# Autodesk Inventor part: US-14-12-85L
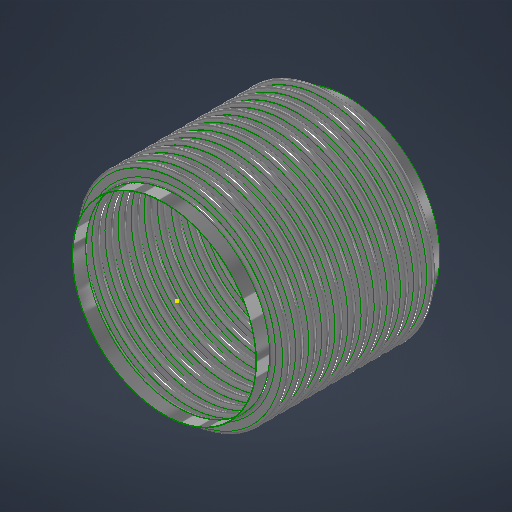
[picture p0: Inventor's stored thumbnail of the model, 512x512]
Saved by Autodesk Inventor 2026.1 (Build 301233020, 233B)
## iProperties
Category: 20 GA (0.036 THICK)
RuleStatus: InUse
Created: 2026-07
Part Number: US-14-12-85L
Project: =STOCK BELLOWS: <Stock Number><SFILL>
Material: ASTM A240-304
Description: =STOCK BELLOWS: <Stock Number>, <SID_> I.D., <SOD_> O.D., <SPLY_> PLY, <Category>, <SNET_CONS> CONS.<PITCH_><STANGENT_> TANGENT<SFILL>
Document SubType Name: Sheet Metal
Designer: LC
Stock Number: U.S-14-12-85L
Surface Area: 659.127 cm^2
Volume: 56.61 cm^3
Sheet Metal Rule: Default
Appearance: STAINLESS STEEL
NET_TUBE: 3.428
COUNTER: 1.500
PBAR: 1.214
PSET: 5.356
PLY: 2
CONS: 2
THK: 0.036
ID: 4.500
OD: 5.500
CONS_: 2
TANGENT: 0.500
PITCH: 0.375
BELLOWS_UPSET: 0.000
NET_CONS: 2
S_CONS: 0
Description_Units: 0
ID_M: 114.30 mm
OD_M: 139.70 mm
THK_M: 0.91 mm
ID_U: 4.500 in
OD_U: 5.500 in
THK_U: 0.036 in
TANGENT2: 0.500
d79: 1.000
d82: 1.000
d83: 26.000
d84: 24.000
d80: 2.571
d81: 10
SID: 2.375
SCONS_: 12
SPITCH: 0.250
SBELLOWS_UPSET: 0.000
SNET_CONS: 12
SS_CONS: 0
SCONS: 8
d174: 8
d177: 0.018
d178: 2.375
d179: 3.000
d180: 0.375
d181: 1.000
d182: 0.000
d190: 8
d191: 1
d192: 1
d193: 8
d194: 0
PART_NUMBER: U.S-14-12-85L
PRESSURE: 85
SIZE: 14.00
STANGENT_: 1.000
d214: 8
d217: 0.030
d218: 6.625
d219: 8.125
d220: 0.500
d221: 1.000
d222: 0.000
d230: 8
d231: 1
d232: 1
d233: 8
d234: 0
STANGENT: 4.000
SPLY_: 1
STHK_: 0.036
SID_: 14.000
SOD_: 16.125
SPITCH_: 1.000
STANGENT__: 1.000
SBELLOWS_UPSET_: 0.000
SDIFF_TAN: 1.000
TAN_TO_TAN: 0.750 in
d252: 2
d275: 2
d287: 0.050
d289: 0.500
d290: 0.000
d263: 2
d265: 1
d268: 2
d269: 0
d286: 2
d288: 1
d291: 2
d292: 0
SOD_NECK: 14 1/16
CFILL: .
SFILL: .
PITCH_: =, <SPITCH_> PITCH,
SREROLL: 0.750
MATTABLE: 20 GA (0.036 THICK)
MESH: ,
CSECT: 2
Author: LC
Keywords: 20 GA (0.036 THICK)
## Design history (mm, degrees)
sketch "Sketch2"
  geometry: L1 (0, -183.595)-(0, 600.956) reference; L2 (58.979, 0)-(57.15, 0); L3 (60.446, -1.467)-(66.554, -1.467); L4 (60.446, -3.296)-(66.554, -3.296); L5 (66.554, -8.058)-(60.446, -8.058); L6 (66.554, -6.229)-(60.446, -6.229); L7 (58.979, -9.525)-(57.15, -9.525); L8 (60.446, 0)-(60.446, -9.525); L9 (66.554, -4.762)-(69.85, -4.763); L10 (57.15, 0)-(57.15, -9.525); L11 (20.376, 102.841)-(20.376, 101.926); L12 (58.262, 488.877)-(58.262, 349.177); L13 (58.262, 479.352)-(58.262, 339.652); L14 (93.133, -58.817)-(93.133, -71.517); L15 (118.746, -66.401)-(118.746, -66.401); L16 (66.554, -6.229)-(66.554, -8.058); L17 (60.446, -6.229)-(60.446, -8.058); L18 (60.446, -7.144)-(66.554, -7.144); L19 (69.85, 0)-(69.85, -9.525); L20 (-66.554, -6.229)-(-66.554, -8.058); L21 (-66.554, -1.467)-(-60.446, -1.467); L22 (-66.554, -3.296)-(-60.446, -3.296); L23 (-60.446, -6.229)-(-66.554, -6.229); L24 (-66.554, -7.144)-(-60.446, -7.144); L25 (-60.446, -8.058)-(-66.554, -8.058); L26 (-60.446, -6.229)-(-60.446, -8.058); L27 (-57.15, -2.522)-(-57.15, -12.047); L28 (-60.446, -4.763)-(-57.15, -4.763); L29 (-66.554, 3.828)-(-66.554, -9.525); L30 (-68.021, 0)-(-69.85, 0); L31 (-69.85, 0)-(-69.85, -9.525); L32 (-68.021, -9.525)-(-69.85, -9.525); A1 r 1.467 centre (60.446, 0) between (58.979, 0) and (60.446, -1.467); A2 r 3.296 centre (60.446, 0) between (57.15, 0) and (60.446, -3.296); A3 r 3.296 centre (66.554, -4.762) between (66.554, -8.058) and (66.554, -1.467); A4 r 1.467 centre (66.554, -4.762) between (66.554, -6.229) and (66.554, -3.296); A5 r 1.467 centre (60.446, -9.525) between (60.446, -8.058) and (58.979, -9.525); A6 r 3.296 centre (60.446, -9.525) between (60.446, -6.229) and (57.15, -9.525); A7 r 2.381 centre (66.554, -4.762) between (66.554, -7.144) and (68.936, -4.762); A8 r 2.381 centre (60.446, -9.525) between (60.446, -7.144) and (58.064, -9.525); A9 r 1.467 centre (-66.554, -9.525) between (-66.554, -8.058) and (-68.021, -9.525); A10 r 1.467 centre (-60.446, -4.763) between (-60.446, -6.229) and (-60.446, -3.296); A11 r 2.381 centre (-60.446, -4.763) between (-60.446, -7.144) and (-58.064, -4.763); A12 r 3.296 centre (-60.446, -4.763) between (-60.446, -8.058) and (-60.446, -1.467); A13 r 2.381 centre (-66.554, -9.525) between (-66.554, -7.144) and (-68.936, -9.525); A14 r 3.296 centre (-66.554, -9.525) between (-66.554, -6.229) and (-69.85, -9.525); A15 r 1.467 centre (-66.554, 0) between (-68.021, 0) and (-66.554, -1.467); A16 r 3.296 centre (-66.554, 0) between (-69.85, 0) and (-66.554, -3.296); 10 further points
  constraints: 62 end point, 38 point on circle, 20 tangent, 16 centre point, 12 parallel, 9 midpoint, 7 vertical, 6 coincident, 6 concentric, 6 point on line, 4 equal radius, 4 perpendicular, 3 horizontal, 1 collinear, 1 horizontal alignment, 10 other
  dimensions: "THK" = 0.9144 distance of L11.start L11.end; "ID" = 114.3 distance of L11.end point (20.376, -12.374); "OD" = 139.7 distance of L12.start L12.end; "PITCH" = 9.525 distance of L12.start L13.start; "TANGENT" = 12.7 distance of L14.start L14.end; "BELLOWS_UPSET" = 0 distance of L15.start L15.end; "d43" = 114.3 diameter of L10 L1 (= ID); "d44" = 139.7 diameter of L9.end L1 (= OD); "d45" = 1.8288 distance between parallel lines of L5 L6 (computed from THK, PLY); "d46" = 3.29565 radius of A3 (computed from PITCH, THK, PLY); "UPSET_PITCH" = 9.525 distance of L2.end L7.end (derived); "SIDEWALL_ANGLE" = 0 deg angle of L3 L9 (derived); "CON_GAP" = 2.9337 distance of point (60.446, -6.229) point (60.446, -3.296) (derived); "TAN1" = 3.74046 dimension on A8 (derived); "TAN2" = 3.74046 dimension on A7 (derived); "LEG1" = 6.1087 distance of L18.start L18.end (derived); "d278" = 1.8288 distance between parallel lines of L25 L23 (derived); "d279" = 3.29565 radius of A12 (derived); "d280" = 9.525 distance of L30.end L31.end (derived); "d281" = 360 deg dimension on L21 L28 (derived); "d282" = 2.9337 distance of point (-66.554, -6.229) point (-66.554, -3.296) (derived); "d283" = 3.74046 dimension on A13 (derived); "d284" = 3.74046 dimension on A11 (derived); "d285" = 6.1087 distance of L24.start L24.end (derived); "d293" = 114.3 diameter of L27 L1 (derived); "d294" = 139.7 diameter of L31 L1 (derived)
  node "Sketch Rectangular Pattern1" dims "d31" = 25.4, "ID" = 114.3
  node "Sketch Rectangular Pattern2" dims "d39" = 25.4, "PITCH" = 9.525
revolve "CONS" stored, may be unused: angle "d48" = 90 deg
node "BELLOW MIDPLANE"
pattern_linear "Rectangular Pattern2" dims "d52" = 9.525 (= UPSET_PITCH)
sketch "Sketch5"
  geometry: C1 r 58.979 at (0, 0) reference; C2 r 57.15 at (0, 0) reference
extrude "TANGENT" new body sketch "Sketch5" distance "d53" = 12.7 (= TANGENT); taper "d54" = 0 deg
revolve "SAMETAN" stored, may be unused: angle "d65" = 90 deg
revolve "DIFFTAN" stored, may be unused: angle "d70" = 90 deg
sketch "Sketch9"
  geometry: L1 (58.391, 0)-(-58.391, 0) reference; L2 (0, -17.78)-(0, 17.78) reference; L3 (41.708, 0)-(-41.708, 0); L4 (41.708, -11.906)-(41.708, 11.906); L5 (29.008, -11.906)-(29.008, 11.906); L6 (15.418, 11.906)-(15.418, -11.906); L7 (-29.008, -11.906)-(-29.008, 11.906); L8 (-41.708, -11.906)-(-41.708, 11.906); L9 (40.914, -11.906)-(40.914, 11.906); L10 (41.708, -11.906)-(40.914, -11.906); L11 (41.708, 11.906)-(40.914, 11.906); L12 (15.815, 11.906)-(15.022, 11.906); L13 (15.022, 11.906)-(15.022, -11.906); L14 (15.022, -11.906)-(15.815, -11.906); L15 (15.815, -11.906)-(15.815, 11.906); L16 (-15.815, 11.906)-(-15.815, -11.906); L17 (-15.418, 11.906)-(-15.418, -11.906); L18 (-15.815, -11.906)-(-15.022, -11.906); L19 (-15.022, -11.906)-(-15.022, 11.906); L20 (-15.022, 11.906)-(-15.815, 11.906); L21 (-41.708, -11.906)-(-40.914, -11.906); L22 (-40.914, -11.906)-(-40.914, 11.906); L23 (-40.914, 11.906)-(-41.708, 11.906); L24 (-41.708, 11.906)-(-41.708, -11.906); L25 (41.708, -0.397)-(-41.708, -0.397); L26 (-41.708, -0.397)-(-41.708, 0.397); L27 (-41.708, 0.397)-(41.708, 0.397); L28 (41.708, 0.397)-(41.708, -0.397); L29 (-41.708, 11.906)-(41.708, 11.906); L30 (41.708, 11.906)-(41.708, 12.7); L31 (41.708, 12.7)-(-41.708, 12.7); L32 (-41.708, 12.7)-(-41.708, 11.906); L33 (41.708, -11.906)-(-41.708, -11.906); L34 (-41.708, -11.906)-(-41.708, -12.7); L35 (-41.708, -12.7)-(41.708, -12.7); L36 (41.708, -12.7)-(41.708, -11.906); 30 further points
  constraints: 68 end point, 13 midpoint, 13 parallel, 8 horizontal, 7 perpendicular, 6 equal length, 3 point on line, 2 vertical, 14 other
  dimensions: "d115" = 23.8125 distance of L4.start L4.end (derived); "d116" = 12.7 distance between parallel lines of L4 L5 (derived); "d117" = 13.58962 distance between parallel lines of L5 L6 (derived); "d125" = 44.42645 distance between parallel lines of L7 L6 (derived); "d127" = 12.7 distance between parallel lines of L8 L7 (derived); "d128" = 26.28962 distance between parallel lines of L6 L4 (derived); "d130" = 83.41607 distance between parallel lines of L8 L4 (derived); "RULER_THK" = 0.79375 distance between parallel lines of L4 L9; "d135" = 0.79375 distance of L13.end L14.end (derived); "d138" = 30.83684 distance of L13.end L16.end (derived); "d143" = 0.79375 distance of L22.end L8.end (derived); "d144" = 0.79375 distance between parallel lines of L27 L25 (derived)
extrude "RULER" join sketch "Sketch9" distance "d149" = 0.79375 (derived); taper "d150" = 0 deg
extrude "BARS" join sketch "Sketch9" distance "d151" = 0.79375 (derived); taper "d152" = 0 deg
pattern_linear "Rectangular Pattern4" dims "d155" = 30.83684 (derived)
sketch "Sketch13"
  geometry: L1 (93.149, -52.467)-(93.149, -77.867); L2 (178.714, 0)-(177.8, 0); L3 (178.714, -25.4)-(177.8, -25.4); L4 (197.98, -19.507)-(184.607, -19.507); L5 (197.98, -18.593)-(184.607, -18.593); L6 (197.98, -12.7)-(204.788, -12.7); L7 (184.607, -5.893)-(197.98, -5.893); L8 (184.607, 0)-(184.607, -25.4); L9 (177.8, 0)-(177.8, -25.4); L10 (58.254, -257.248)-(58.254, -666.823); L11 (58.254, -282.648)-(58.254, -692.223); L12 (58.254, -333.448)-(58.254, -743.023); L13 (58.254, -358.848)-(58.254, -768.423); L14 (58.254, -384.248)-(58.254, -793.823); L15 (58.254, -409.648)-(58.254, -819.223); L16 (58.254, -435.048)-(58.254, -844.623); L17 (58.254, -308.048)-(58.254, -717.623); L18 (20.376, 102.841)-(20.376, 101.926); L19 (184.607, -6.807)-(197.98, -6.807); L20 (0, -1008.715)-(0, 288.1) reference; L21 (-37.783, 0)-(226.695, 0) reference; A1 r 5.893 centre (184.607, 0) between (178.714, 0) and (184.607, -5.893); A2 r 5.893 centre (184.607, -25.4) between (184.607, -19.507) and (178.714, -25.4); A3 r 6.807 centre (184.607, -25.4) between (184.607, -18.593) and (177.8, -25.4); A4 r 5.893 centre (197.98, -12.7) between (197.98, -18.593) and (197.98, -6.807); A5 r 6.807 centre (197.98, -12.7) between (197.98, -19.507) and (197.98, -5.893); A6 r 6.807 centre (184.607, 0) between (177.8, 0) and (184.607, -6.807); 6 further points; 1 other entity
  constraints: 38 end point, 15 point on circle, 9 tangent, 6 centre point, 6 parallel, 5 vertical alignment, 4 point on line, 4 vertical, 3 coincident, 3 concentric, 2 collinear, 2 equal radius, 1 horizontal, 1 perpendicular, 23 other
  dimensions: "SBELLOWS_UPSET_" = 0 distance of point (118.762, -66.401) point (118.762, -66.401); "STOTAL_THK_BELLOW__" = 0.9144 distance between parallel lines of L4 L5 (derived); "d224" = 6.8072 radius of A5 (derived); "d225" = 25.4 distance of L2.end L3.end (derived); "SSIDEWALL_ANGLE_" = 0 deg angle of L7 L6 (derived); "SSCON_GAP_" = 11.7856 distance of point (184.607, -18.593) point (184.607, -6.807) (derived); "d235" = 355.6 diameter of L9 L20 (derived); "d236" = 409.575 diameter of L6.end L20 (derived)
  node "Sketch Rectangular Pattern4" dims "d228" = 25.4
  node "Sketch Rectangular Pattern5" dims "d229" = 25.4
revolve "SBELLOW" stored, may be unused: angle "d197" = 90 deg
pattern_linear "Rectangular Pattern5" dims "d204" = 25.4 (derived)
revolve "STANGENT" stored, may be unused: angle "d240" = 90 deg
revolve "SSAMETAN" stored, may be unused: angle "d241" = 90 deg
revolve "SDIFFTAN" stored, may be unused: angle "d246" = 90 deg
revolve "INVCON" stored, may be unused: angle "d295" = 90 deg
pattern_linear "Rectangular Pattern6" dims "d298" = 9.525 (derived)
revolve "INVTANGENT" stored, may be unused: angle "d302" = 90 deg
revolve "INVSAMETAN" stored, may be unused: angle "d307" = 90 deg
revolve "INVDIFFTAN" stored, may be unused: angle "d312" = 90 deg
sketch "ID BELLOW MOUNT CALC"
  geometry: L1 (44.45, 0)-(38.1, 0); L2 (38.1, 0)-(38.1, 12.7); L3 (38.1, 12.7)-(44.45, 12.7); L4 (44.45, 12.7)-(44.45, 0); L5 (36.513, 12.7)-(34.684, 12.7); L6 (34.684, 12.7)-(34.684, 0); L7 (34.684, 0)-(36.513, 0); L8 (36.513, 0)-(36.513, 12.7); L9 (0, -2.54)-(0, 15.24) reference; L10 (-8.89, 0)-(53.34, 0) reference; 1 further point
  constraints: 16 end point, 5 parallel, 2 collinear, 2 horizontal, 2 perpendicular
  dimensions: "d314" = 12.7 distance of L5.end L6.end (derived); "d315" = 1.8288 distance of L5.start L5.end (derived); "IG" = 1.5875 distance between parallel lines of L2 L8; "PIPE_OD" = 88.9 diameter of L4 L9; "PIPE_WALL" = 6.35 distance of L2.end L3.end; "ID_MT_BELLOW" = 69.3674 diameter of L6 L9 (derived)
revolve "CFILL" stored, may be unused: angle "d320" = 90 deg
pattern_linear "Rectangular Pattern7" dims "d323" = 9.525 (derived)
revolve "SFILL" stored, may be unused: angle "d324" = 90 deg
pattern_linear "Rectangular Pattern8" dims "d327" = 25.4 (derived)
node "STOCK BELLOW MIDPLANE"
sketch "Sketch21"
  geometry: L1 (0, -100.013)-(0, 100.013) reference; L2 (-100.013, 0)-(100.013, 0) reference; L3 (-0.099, 71.437)-(0.099, 71.437); L4 (0.099, 71.437)-(0.099, 55.562); L5 (0.099, 55.562)-(-0.099, 55.562); L6 (-0.099, 55.562)-(-0.099, 71.437); C1 r 55.562 at (0, 0); C2 r 71.437 at (0, 0); 3 further points
  constraints: 8 end point, 2 centre point, 2 coincident, 2 parallel, 2 tangent, 1 horizontal, 1 perpendicular, 1 other
  dimensions: "d329" = 111.125 diameter of C1 (derived); "d330" = 142.875 diameter of C2 (derived); "d331" = 0.19844 distance of L3.start L3.end
extrude "CLAMSHELL" cut sketch "Sketch21" extent not by distance; stored distance "d332" = 0; taper "d333" = 0 deg
pattern_circular "Circular Pattern1" dims angle "d335" = 180 deg (derived)
node "BELLOW"
sketch "Sketch6"
  geometry: L1 (-19.05, 58.979)-(-6.35, 58.979); L2 (-6.35, 58.979)-(-6.35, 57.15); L3 (-6.35, 57.15)-(-19.05, 57.15); L4 (-19.05, 57.15)-(-19.05, 58.979); L5 (2.54, 0)-(-59.69, 0) reference; L6 (-38.1, -108.388)-(-38.1, 156.601) reference; 1 further point
  constraints: 8 end point, 2 parallel, 1 horizontal, 1 perpendicular
  dimensions: "d61" = 12.7 distance of L2.end L3.end (derived); "d62" = 1.8288 distance of L1.end L2.end (derived); "d63" = 114.3 diameter of L3 L5 (derived); "d64" = 19.05 distance between parallel lines of L4 L6 (derived)
sketch "Sketch12"
  geometry: 1 further point
sketch "Sketch14"
  geometry: L1 (-25.4, 178.714)-(0, 178.714); L2 (0, 178.714)-(0, 177.8); L3 (0, 177.8)-(-25.4, 177.8); L4 (-25.4, 177.8)-(-25.4, 178.714); L5 (5.08, 0)-(-30.48, 0) reference; L6 (0, -32.568)-(0, 195.407) reference; 1 further point
  constraints: 8 end point, 2 parallel, 1 collinear, 1 horizontal, 1 perpendicular
  dimensions: "d237" = 0.9144 distance of L3.end L1.start (derived); "d238" = 355.6 diameter of L3 L5 (derived); "d239" = 25.4 distance of L1.start L1.end (derived); "SOD_NECK" = 357.4288 diameter of L1 L5 (derived)
sketch "Sketch15"
  geometry: L1 (-32.568, 0)-(195.407, 0) reference; L2 (177.8, -304.8)-(178.714, -304.8); L3 (178.714, -304.8)-(178.714, -330.2); L4 (178.714, -330.2)-(177.8, -330.2); L5 (177.8, -330.2)-(177.8, -304.8); L6 (0, -398.78)-(0, 81.28) reference; 1 further point
  constraints: 8 end point, 2 parallel, 1 horizontal, 1 perpendicular
  dimensions: "d205" = 25.4 distance of L4.end L2.start (derived); "d206" = 0.9144 distance of L3.end L4.end (derived); "d207" = 355.6 diameter of L5 L6 (derived); "d208" = 304.8 distance between parallel lines of L1 L2 (derived)
node "TANGENT_"
node "SAME_TAN"
sketch "Sketch8"
  geometry: L1 (58.979, -19.05)-(57.15, -19.05); L2 (57.15, -19.05)-(57.15, -31.75); L3 (57.15, -31.75)-(58.979, -31.75); L4 (58.979, -31.75)-(58.979, -19.05); L5 (0, -40.64)-(0, 21.59) reference; L6 (-108.388, 0)-(156.601, 0) reference; 1 further point
  constraints: 8 end point, 2 parallel, 1 horizontal, 1 perpendicular
  dimensions: "d66" = 114.3 diameter of L2 L5 (derived); "TOTAL_THK_BELLOW" = 1.8288 distance of L2.end L3.end (derived); "d68" = 19.05 distance between parallel lines of L1 L6 (derived); "d69" = 12.7 distance of L1.end L2.end (derived)
node "DIFF_TAN"
node "Sketch Rectangular Pattern3" dims "d138" = 30.83684 (derived), "d141" = 25.4
node "SBELLOW_"
node "STANGENT_"
node "SSAME_TAN"
sketch "Sketch16"
  geometry: L1 (178.714, -304.8)-(177.8, -304.8); L2 (177.8, -304.8)-(177.8, -330.2); L3 (177.8, -330.2)-(178.714, -330.2); L4 (178.714, -330.2)-(178.714, -304.8); L5 (0, -398.78)-(0, 81.28) reference; L6 (-32.568, 0)-(195.407, 0) reference; 1 further point
  constraints: 8 end point, 2 parallel, 1 horizontal, 1 perpendicular
  dimensions: "SDIFF_TAN" = 25.4 distance of L3.end L1.start; "d243" = 0.9144 distance of L2.end L3.end (derived); "d244" = 304.8 distance between parallel lines of L1 L6 (derived); "d245" = 355.6 diameter of L2 L5 (derived)
node "SDIFF_TAN"
body "Solid15"
sketch "Sketch17"
  geometry: L1 (69.85, 12.7)-(68.021, 12.7); L2 (68.021, 12.7)-(68.021, 0); L3 (68.021, 0)-(69.85, 0); L4 (69.85, 0)-(69.85, 12.7); L5 (0, -2.54)-(0, 15.24) reference; L6 (-13.97, 0)-(83.82, 0) reference; 2 further points
  constraints: 8 end point, 2 parallel, 1 horizontal, 1 midpoint, 1 perpendicular, 1 point on line
  dimensions: "INVTANGENT" = 12.7 distance of L3.end L1.start (derived); "d300" = 1.8288 distance of L1.start L1.end (derived); "d301" = 139.7 diameter of L4 L5 (derived)
body "Solid16"
sketch "Sketch18"
  geometry: L1 (69.85, -19.05)-(68.021, -19.05); L2 (68.021, -19.05)-(68.021, -31.75); L3 (68.021, -31.75)-(69.85, -31.75); L4 (69.85, -31.75)-(69.85, -19.05); L5 (-13.97, 0)-(83.82, 0) reference; L6 (0, -40.64)-(0, 21.59) reference; 1 further point
  constraints: 8 end point, 2 parallel, 1 horizontal, 1 perpendicular
  dimensions: "d303" = 19.05 distance between parallel lines of L1 L5 (derived); "d304" = 12.7 distance of L3.end L1.start (derived); "d305" = 1.8288 distance of L2.end L3.end (derived); "d306" = 139.7 diameter of L4 L6 (derived)
body "Solid17"
sketch "Sketch19"
  geometry: L1 (69.85, -19.05)-(68.021, -19.05); L2 (68.021, -19.05)-(68.021, -31.75); L3 (68.021, -31.75)-(69.85, -31.75); L4 (69.85, -31.75)-(69.85, -19.05); L5 (0, -40.64)-(0, 21.59) reference; L6 (-13.97, 0)-(83.82, 0) reference; 1 further point
  constraints: 8 end point, 2 parallel, 1 horizontal, 1 perpendicular
  dimensions: "d308" = 12.7 distance of L1.end L2.end (derived); "d309" = 139.7 diameter of L4 L5 (derived); "d310" = 1.8288 distance of L2.end L3.end (derived); "d311" = 19.05 distance between parallel lines of L1 L6 (derived)
body "Solid18"
body "Solid19"
body "Solid20"
other parameters: "BMPL" = -152.4, "PSET" = 136.0424 (computed from OD, THK, PLY) [user parameter], "PBAR" = 30.83684 (= 0.570796 x PITCH + OD - ID) [user parameter; used in 1 equation term], "COUNTER" = 15 [user parameter], "NET_TUBE" = 87.07367 (computed from CONS_, PBAR, TANGENT) [user parameter], "S_CONS" = 0 [user parameter; used in 1 equation term], "ID_M" = 114.3 (= ID) [user parameter], "OD_M" = 139.7 (= OD) [user parameter], "THK_M" = 0.9144 (= THK) [user parameter], "ID_U" = 114.3 (= ID) [user parameter], "OD_U" = 139.7 (= OD) [user parameter], "THK_U" = 0.9144 (= THK) [user parameter], "D_UNITS" = 0 [user parameter], "TANGENT2" = 12.7 [user parameter], "TAN_TO_TAN" = 19.05 [user parameter], "OD_NECK" = 117.9576 [user parameter], "d79" = 25.4, "d80" = 65.29823 [user parameter], "d82" = 25.4, "d83" = 660.4, "d84" = 609.6, "sa_0" = 4, "FRAME_THK" = 0.79375 [user parameter], "CON_FLAT" = 13.58962 [user parameter], "SID" = 60.325 [user parameter], "SPITCH" = 6.35 [user parameter], "STANGENT_" = 25.4 [user parameter], "SBELLOWS_UPSET" = 0 [user parameter], "SS_CONS" = 0 [user parameter], "STAN_TO_TAN_" = 304.8 [user parameter], "d100" = 0.9144 [user parameter], "d191" = 25.4 [user parameter], "d194" = 0 [user parameter], "STANGENT" = 101.6 [user parameter], "d234" = 0 [user parameter], "SUPSET_PITCH_" = 25.4 [user parameter], "d269" = 0 [user parameter], "d287" = 1.27, "d289" = 12.7, "d290" = 0, "d292" = 0 [user parameter], "Thickness" = 3.048 (derived), "KFactor" = 4.4, "BendRadius" = 3.048 (derived), "BendReliefWidth" = 3.048 (derived), "BendReliefDepth" = 1.524 (derived), "CornerReliefSize" = 12.192 (derived), "SeamGap" = 0.00508, "MinimumRemnant" = 6.096 (derived), "TransitionRadius" = 3.048 (derived), "JacobiRadiusSize" = 3.048 (derived), "GapSize" = 3.048 (derived), "SREROLL" = 19.05 [user parameter], "CUR_STK_PITCH" = 25.4 [user parameter], "d328" = -152.4 (derived), "CSECTDEG" = 180 deg [user parameter]
